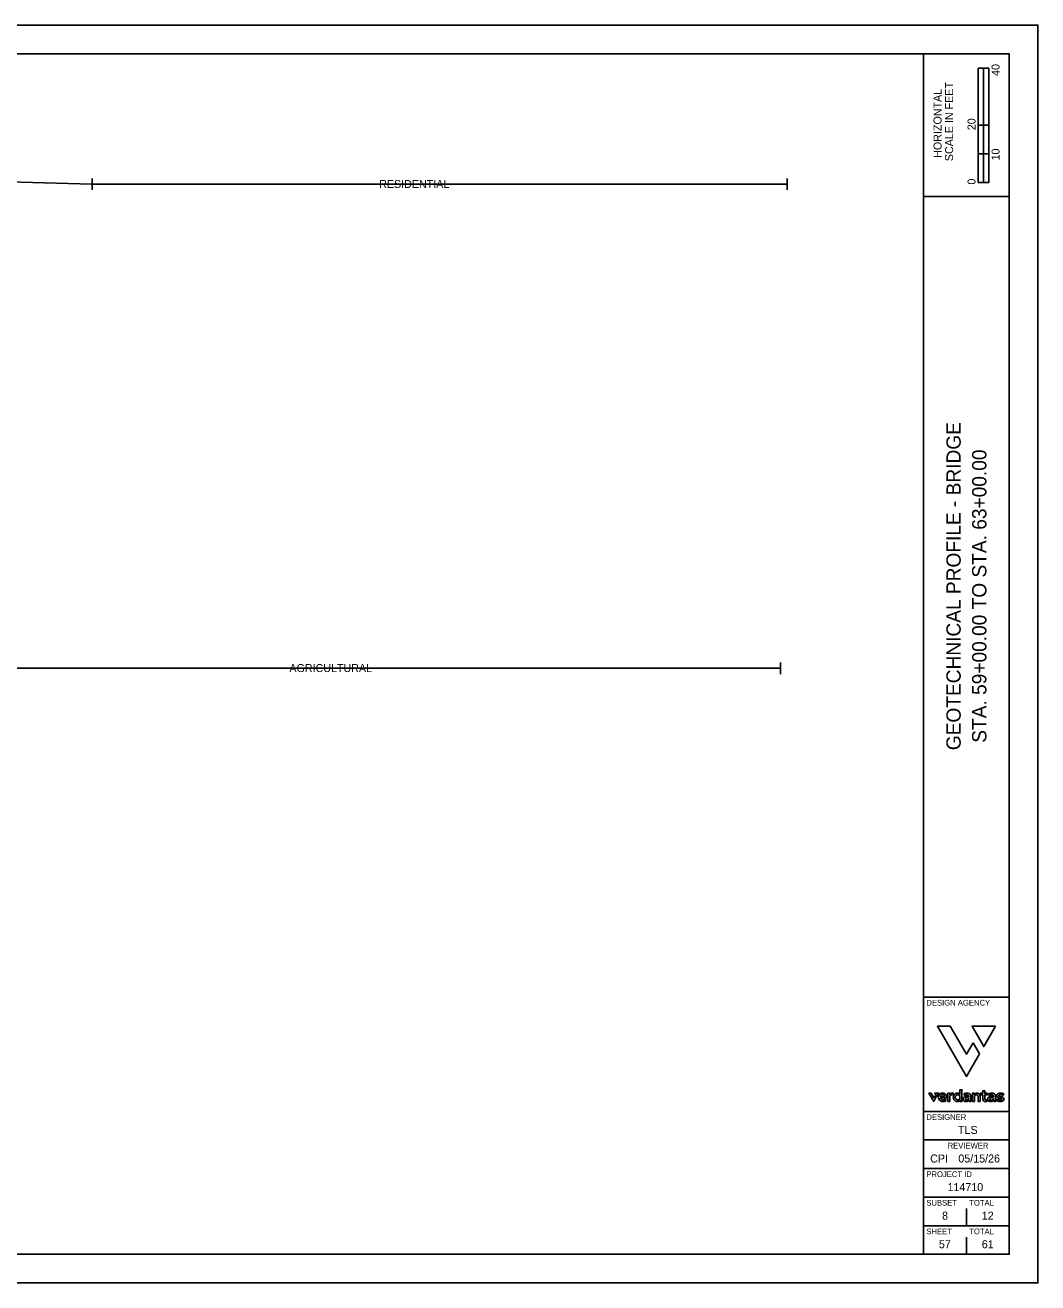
# Model space of a CAD drawing. Extents: x -1.4 to 34, y 0 to 22.
# Drawn here: x 16.28 to 34, y 0 to 22 of the extents above; entities that cross this region are included whole.
import ezdxf

# ---------------------------------------------------------------- set-up
doc = ezdxf.new("R2010")
doc.units = 0
for name, color, linetype in [('SH_Border', 7, 'Continuous'), ('SH_Cut_Line', 7, 'Continuous'), ('SH_Data', 7, 'Continuous'), ('SH_Text', 7, 'Continuous')]:
    doc.layers.add(name, color=color, linetype=linetype)

msp = doc.modelspace()

# ---------------------------------------------------------------- linework, layer by layer
at = {"layer": 'SH_Border'}
for p, q in [((32, 0.5), (32, 21.5)), ((32, 19), (33.5, 19)), ((32, 5), (33.5, 5)), ((32, 3), (33.5, 3)), ((32, 2.5), (33.5, 2.5)), ((32, 2), (33.5, 2)), ((32, 1.5), (33.5, 1.5)), ((32, 1), (33.5, 1))]:
    msp.add_line(p, q, dxfattribs=at)
msp.add_lwpolyline([(1.5, 21.5), (33.5, 21.5), (33.5, 0.5), (1.5, 0.5)], close=True, dxfattribs=at)
at = {"layer": 'SH_Cut_Line'}
msp.add_lwpolyline([(0, 0), (34, 0), (34, 22), (0, 22)], close=True, dxfattribs=at)
at = {"layer": 'SH_Data'}
for p, q in [((32.957, 19.25), (32.957, 21.25)), ((33.144, 21.25), (32.957, 21.25)), ((32.957, 20.25), (32.957, 21.25)), ((32.957, 21.25), (33.05, 21.25)), ((33.05, 21.25), (33.051, 21.25)), ((33.051, 21.25), (33.051, 20.25)), ((33.144, 21.25), (33.144, 19.25)), ((33.051, 20.25), (32.957, 20.25)), ((33.143, 20.25), (33.05, 20.25)), ((33.05, 20.25), (33.05, 19.75)), ((33.143, 19.75), (33.143, 20.25)), ((33.05, 19.75), (32.957, 19.75)), ((32.957, 19.75), (32.957, 19.25)), ((33.05, 19.25), (33.05, 19.75)), ((33.05, 19.75), (33.143, 19.75)), ((33.144, 19.25), (32.957, 19.25)), ((32.957, 19.25), (33.05, 19.25)), ((32.75, 4), (32.75, 4)), ((32.75, 1), (32.75, 1.3)), ((32.375, 0.675), (32.375, 0.675)), ((32.75, 0.5), (32.75, 0.8))]:
    msp.add_line(p, q, dxfattribs=at)
at = {"layer": 'SH_Text'}
for p, q in [((4.615, 19.565), (17.458, 19.219)), ((17.458, 19.319), (17.458, 19.119)), ((17.458, 19.219), (29.616, 19.219)), ((29.616, 19.319), (29.616, 19.119)), ((29.5, 10.85), (29.5, 10.65)), ((32.509, 3.288), (32.525, 3.316)), ((32.712, 3.311), (32.703, 3.308)), ((33.146, 3.311), (33.137, 3.308)), ((33.385, 3.28), (33.402, 3.304)), ((32.292, 3.234), (32.407, 3.234)), ((32.373, 3.256), (32.293, 3.256)), ((32.396, 3.189), (32.379, 3.213)), ((32.637, 3.267), (32.637, 3.222)), ((32.793, 3.263), (32.793, 3.251)), ((32.793, 3.232), (32.793, 3.215)), ((33.119, 3.178), (33.107, 3.204)), ((33.227, 3.263), (33.227, 3.251)), ((33.227, 3.232), (33.227, 3.215)), ((33.295, 3.218), (33.276, 3.194)), ((33.332, 3.233), (33.347, 3.23)), ((33.364, 3.255), (33.34, 3.26))]:
    msp.add_line(p, q, dxfattribs=at)
for points in [[(4.5, 10.75), (14.999, 10.75), (29.5, 10.75)], [(32.866, 4.201), (32.75, 4), (32.468, 4.488), (32.243, 4.488), (32.75, 3.61), (32.979, 4.006), (32.866, 4.201)], [(33.257, 4.488), (32.848, 4.488), (33.053, 4.134), (33.257, 4.488)], [(32.199, 3.272), (32.18, 3.239), (32.133, 3.32), (32.095, 3.32), (32.18, 3.174), (32.218, 3.24), (32.199, 3.272)], [(32.264, 3.32), (32.196, 3.32), (32.23, 3.261), (32.264, 3.32)], [(32.458, 3.286), (32.458, 3.316), (32.427, 3.316), (32.427, 3.173), (32.46, 3.173), (32.46, 3.268)], [(32.458, 3.286), (32.458, 3.316), (32.427, 3.316), (32.427, 3.173), (32.46, 3.173), (32.46, 3.268)], [(32.509, 3.288), (32.525, 3.316)], [(32.637, 3.297), (32.637, 3.377), (32.671, 3.377), (32.671, 3.173), (32.64, 3.173), (32.64, 3.199)], [(32.64, 3.199), (32.64, 3.173), (32.671, 3.173), (32.671, 3.377), (32.637, 3.377), (32.637, 3.297)], [(32.712, 3.311), (32.703, 3.308)], [(32.703, 3.308), (32.714, 3.281), (32.721, 3.284)], [(32.703, 3.308), (32.714, 3.281), (32.721, 3.284)], [(32.887, 3.288), (32.887, 3.316), (32.856, 3.316), (32.856, 3.173), (32.89, 3.173), (32.89, 3.269)], [(32.887, 3.288), (32.887, 3.316), (32.856, 3.316), (32.856, 3.173), (32.89, 3.173), (32.89, 3.269)], [(33.07, 3.226), (33.07, 3.287), (33.116, 3.287), (33.116, 3.316), (33.07, 3.316), (33.07, 3.36), (33.036, 3.36), (33.036, 3.316), (32.991, 3.316), (33.009, 3.287), (33.036, 3.287), (33.036, 3.22)], [(33.07, 3.226), (33.07, 3.287), (33.116, 3.287), (33.116, 3.316), (33.07, 3.316), (33.07, 3.36), (33.036, 3.36), (33.036, 3.316), (32.991, 3.316), (33.009, 3.287), (33.036, 3.287), (33.036, 3.22)], [(33.146, 3.311), (33.137, 3.308)], [(33.137, 3.308), (33.148, 3.281), (33.155, 3.284)], [(33.137, 3.308), (33.148, 3.281), (33.155, 3.284)], [(33.385, 3.28), (33.402, 3.304), (33.401, 3.304)], [(32.292, 3.234), (32.407, 3.234)], [(32.293, 3.256), (32.373, 3.256)], [(32.396, 3.189), (32.379, 3.213)], [(32.637, 3.267), (32.637, 3.222)], [(32.793, 3.263), (32.793, 3.251)], [(32.793, 3.215), (32.793, 3.232)], [(32.796, 3.196), (32.796, 3.173), (32.827, 3.173), (32.827, 3.267)], [(32.796, 3.196), (32.796, 3.173), (32.827, 3.173), (32.827, 3.267)], [(32.954, 3.257), (32.954, 3.173), (32.988, 3.173), (32.988, 3.267)], [(32.954, 3.257), (32.954, 3.173), (32.988, 3.173), (32.988, 3.267)], [(33.119, 3.178), (33.107, 3.204)], [(33.227, 3.263), (33.227, 3.251)], [(33.227, 3.215), (33.227, 3.232)], [(33.23, 3.196), (33.23, 3.173), (33.261, 3.173), (33.261, 3.267)], [(33.23, 3.196), (33.23, 3.173), (33.261, 3.173), (33.261, 3.267)], [(33.296, 3.216), (33.295, 3.218), (33.276, 3.194), (33.279, 3.192)], [(33.332, 3.233), (33.347, 3.23)], [(33.364, 3.255), (33.34, 3.26)], [(33.383, 3.281), (33.385, 3.28)]]:
    msp.add_lwpolyline(points, dxfattribs=at)
for points in [[(32.866, 4.201), (32.75, 4), (32.468, 4.488), (32.243, 4.488), (32.75, 3.61), (32.979, 4.006)], [(32.199, 3.272), (32.18, 3.239), (32.133, 3.32), (32.095, 3.32), (32.18, 3.174), (32.218, 3.24)], [(32.23, 3.261), (32.196, 3.32), (32.264, 3.32)]]:
    msp.add_lwpolyline(points, close=True, dxfattribs=at)
for centre, radius, start, end in [((32.333, 3.245), 0.0747, 351.0446, 190.2577), ((32.333, 3.245), 0.0747, 351.0446, 190.2577), ((32.504, 3.274), 0.0471, 62.6524, 165.2929), ((32.504, 3.274), 0.0471, 62.6524, 165.2929), ((32.595, 3.245), 0.075, 92.7719, 272.9779), ((32.595, 3.245), 0.075, 92.7719, 272.9779), ((32.593, 3.266), 0.0536, 34.2843, 91.2723), ((32.593, 3.266), 0.0536, 34.2843, 91.2723), ((32.763, 3.171), 0.149, 90.9467, 109.8354), ((32.763, 3.171), 0.149, 90.9467, 109.8354), ((32.762, 3.224), 0.0962, 70.8128, 90.9317), ((32.762, 3.224), 0.0962, 70.8128, 90.9317), ((32.779, 3.269), 0.0479, 358.076, 72.8642), ((32.779, 3.269), 0.0479, 358.076, 72.8642), ((32.936, 3.268), 0.0527, 358.9896, 156.9111), ((32.936, 3.268), 0.0527, 358.9896, 156.9111), ((33.197, 3.171), 0.149, 90.9467, 109.8354), ((33.197, 3.171), 0.149, 90.9467, 109.8354), ((33.196, 3.224), 0.0962, 70.8128, 90.9317), ((33.196, 3.224), 0.0962, 70.8128, 90.9317), ((33.213, 3.269), 0.0479, 358.076, 72.8642), ((33.213, 3.269), 0.0479, 358.076, 72.8642), ((33.332, 3.267), 0.0503, 113.3692, 147.807), ((33.332, 3.267), 0.0503, 113.3692, 147.807), ((33.346, 3.235), 0.0854, 89.0109, 113.56), ((33.347, 3.233), 0.0867, 89.2017, 113.3692), ((33.348, 3.221), 0.0985, 57.2233, 89.842), ((33.348, 3.222), 0.0979, 56.3984, 89.8856), ((32.342, 3.255), 0.0854, 195.6668, 309.3699), ((32.342, 3.255), 0.0854, 195.6668, 309.3699), ((32.343, 3.253), 0.054, 200.9232, 312.7391), ((32.343, 3.253), 0.054, 200.9232, 312.7391), ((32.333, 3.25), 0.0407, 8.8378, 171.1622), ((32.333, 3.25), 0.0407, 8.8378, 171.1622), ((32.496, 3.249), 0.0409, 72.1384, 152.0408), ((32.496, 3.249), 0.0409, 72.1384, 152.0408), ((32.6, 3.245), 0.0446, 86.4529, 275.055), ((32.6, 3.245), 0.0446, 86.4529, 275.055), ((32.594, 3.22), 0.0503, 275.3084, 334.5252), ((32.594, 3.22), 0.0503, 275.3084, 334.5252), ((32.599, 3.246), 0.0439, 29.9007, 85.5797), ((32.599, 3.246), 0.0439, 29.9007, 85.5797), ((32.599, 3.244), 0.0441, 276.0666, 330.041), ((32.599, 3.244), 0.0441, 276.0666, 330.041), ((32.736, 3.216), 0.0444, 111.6764, 249.7268), ((32.736, 3.216), 0.0444, 111.6764, 249.7268), ((32.751, 3.182), 0.0814, 58.3497, 112.4708), ((32.751, 3.182), 0.0814, 58.3497, 112.4708), ((32.744, 3.234), 0.0643, 248.2774, 323.7949), ((32.744, 3.234), 0.0643, 248.2774, 323.7949), ((32.762, 3.177), 0.114, 91.6616, 110.8714), ((32.762, 3.177), 0.114, 91.6616, 110.8714), ((32.747, 3.218), 0.021, 92.327, 265.3778), ((32.747, 3.218), 0.021, 92.327, 265.3778), ((32.759, 3.162), 0.0786, 63.8372, 98.8746), ((32.759, 3.162), 0.0786, 63.8372, 98.8746), ((32.755, 3.244), 0.0478, 258.1247, 322.3678), ((32.755, 3.244), 0.0478, 258.1247, 322.3678), ((32.758, 3.242), 0.0486, 73.2522, 89.9971), ((32.758, 3.242), 0.0486, 73.2522, 89.9971), ((32.765, 3.262), 0.0281, 2.9671, 75.223), ((32.765, 3.262), 0.0281, 2.9671, 75.223), ((32.922, 3.254), 0.0358, 90.3466, 154.9113), ((32.922, 3.254), 0.0358, 90.3466, 154.9113), ((32.924, 3.257), 0.0325, 47.3049, 92.9688), ((32.924, 3.257), 0.0325, 47.3049, 92.9688), ((32.922, 3.259), 0.0325, 356.9739, 42.7421), ((32.922, 3.259), 0.0325, 356.9739, 42.7421), ((33.084, 3.218), 0.0482, 177.8641, 271.6213), ((33.084, 3.218), 0.0482, 177.8641, 271.6213), ((33.094, 3.224), 0.0236, 175.0692, 266.3548), ((33.094, 3.224), 0.0236, 175.0692, 266.3548), ((33.086, 3.24), 0.0704, 269.5424, 298.2495), ((33.086, 3.24), 0.0704, 269.5424, 298.2495), ((33.091, 3.232), 0.0324, 271.8638, 299.9651), ((33.091, 3.232), 0.0324, 271.8638, 299.9651), ((33.17, 3.216), 0.0444, 111.6764, 249.7268), ((33.17, 3.216), 0.0444, 111.6764, 249.7268), ((33.184, 3.182), 0.0814, 58.3497, 112.4708), ((33.184, 3.182), 0.0814, 58.3497, 112.4708), ((33.178, 3.234), 0.0643, 248.2774, 323.7949), ((33.178, 3.234), 0.0643, 248.2774, 323.7949), ((33.196, 3.177), 0.114, 91.6616, 110.8714), ((33.196, 3.177), 0.114, 91.6616, 110.8714), ((33.181, 3.218), 0.021, 92.327, 265.3778), ((33.181, 3.218), 0.021, 92.327, 265.3778), ((33.189, 3.244), 0.0478, 258.1247, 322.3678), ((33.189, 3.244), 0.0478, 258.1247, 322.3678), ((33.192, 3.162), 0.0786, 63.8372, 98.8746), ((33.192, 3.162), 0.0786, 63.8372, 98.8746), ((33.192, 3.242), 0.0486, 73.2522, 89.9971), ((33.192, 3.242), 0.0486, 73.2522, 89.9971), ((33.199, 3.262), 0.0281, 2.9671, 75.223), ((33.199, 3.262), 0.0281, 2.9671, 75.223), ((33.34, 3.266), 0.0958, 227.8814, 270.5651), ((33.34, 3.267), 0.0971, 230.5166, 270.4341), ((33.319, 3.276), 0.0344, 148.9453, 227.6829), ((33.319, 3.276), 0.0344, 148.9453, 227.6829), ((33.344, 3.268), 0.0698, 225.2875, 267.0077), ((33.347, 3.311), 0.0789, 230.1259, 259.7023), ((33.347, 3.311), 0.0789, 230.1259, 259.7023), ((33.344, 3.268), 0.0699, 227.363, 266.9244), ((33.329, 3.276), 0.0111, 134.7822, 240.4366), ((33.329, 3.276), 0.0111, 134.7822, 240.4366), ((33.339, 3.265), 0.0251, 103.8561, 133.7191), ((33.339, 3.265), 0.0251, 103.8561, 133.7191), ((33.352, 3.321), 0.0614, 242.9002, 259.3831), ((33.352, 3.321), 0.0614, 242.9002, 259.3831), ((33.347, 3.239), 0.0526, 89.0539, 105.6921), ((33.347, 3.239), 0.0526, 89.0539, 105.6921), ((33.343, 3.247), 0.0491, 267.0077, 296.3112), ((33.343, 3.247), 0.0491, 267.0077, 296.3112), ((33.343, 3.259), 0.0897, 269.0192, 292.9257), ((33.342, 3.26), 0.0904, 269.1171, 292.8278), ((33.336, 3.16), 0.0712, 68.1863, 80.6328), ((33.336, 3.16), 0.0712, 68.1863, 80.6328), ((33.346, 3.221), 0.0711, 58.1233, 88.1135), ((33.346, 3.221), 0.071, 56.2397, 88.1242), ((33.359, 3.214), 0.0124, 296.9165, 73.602), ((33.359, 3.214), 0.0124, 296.9165, 73.602), ((33.342, 3.16), 0.0972, 64.0447, 77.2149), ((33.342, 3.16), 0.0972, 64.0447, 77.2149), ((33.357, 3.226), 0.0533, 292.8278, 320.7157), ((33.357, 3.226), 0.0533, 292.8278, 320.7157), ((33.369, 3.215), 0.0369, 322.7092, 64.2166), ((33.369, 3.214), 0.037, 322.8811, 64.0447)]:
    msp.add_arc(centre, radius, start, end, dxfattribs=at)

# ---------------------------------------------------------------- texts
at = {"layer": 'SH_Data'}
for s, height, p in [('40', 0.14, (33.33, 21.112)), ('SCALE IN FEET', 0.14, (32.517, 19.621)), ('HORIZONTAL', 0.14, (32.315, 19.679)), ('20', 0.14, (32.91, 20.162)), ('10', 0.14, (33.33, 19.633)), ('0', 0.14, (32.91, 19.211)), ('GEOTECHNICAL PROFILE - BRIDGE', 0.25, (32.65, 9.317)), ('STA. 59+00.00 TO STA. 63+00.00', 0.25, (33.1, 9.448))]:
    msp.add_text(s, height=height, rotation=90, dxfattribs=at).set_placement(p)
for s, height, p in [('DESIGN AGENCY', 0.1, (32.05, 4.85)), ('DESIGNER', 0.1, (32.05, 2.85)), ('TLS', 0.14, (32.603, 2.605)), ('REVIEWER', 0.1, (32.422, 2.35)), ('CPI', 0.14, (32.116, 2.105)), ('05/15/26', 0.14, (32.609, 2.105)), ('PROJECT ID', 0.1, (32.05, 1.85)), ('114710', 0.14, (32.419, 1.605)), ('SUBSET', 0.1, (32.05, 1.35)), ('TOTAL', 0.1, (32.8, 1.35)), ('8', 0.14, (32.324, 1.105)), ('12', 0.14, (33.019, 1.105)), ('SHEET', 0.1, (32.05, 0.85)), ('TOTAL', 0.1, (32.8, 0.85)), ('57', 0.14, (32.268, 0.605)), ('61', 0.14, (33.019, 0.605))]:
    msp.add_text(s, height=height, dxfattribs=at).set_placement(p)
at = {"layer": 'SH_Text'}
for s, p in [('RESIDENTIAL', (22.476, 19.152)), ('AGRICULTURAL', (20.906, 10.684))]:
    msp.add_text(s, height=0.14, dxfattribs=at).set_placement(p)

doc.saveas('drawing.dxf')
